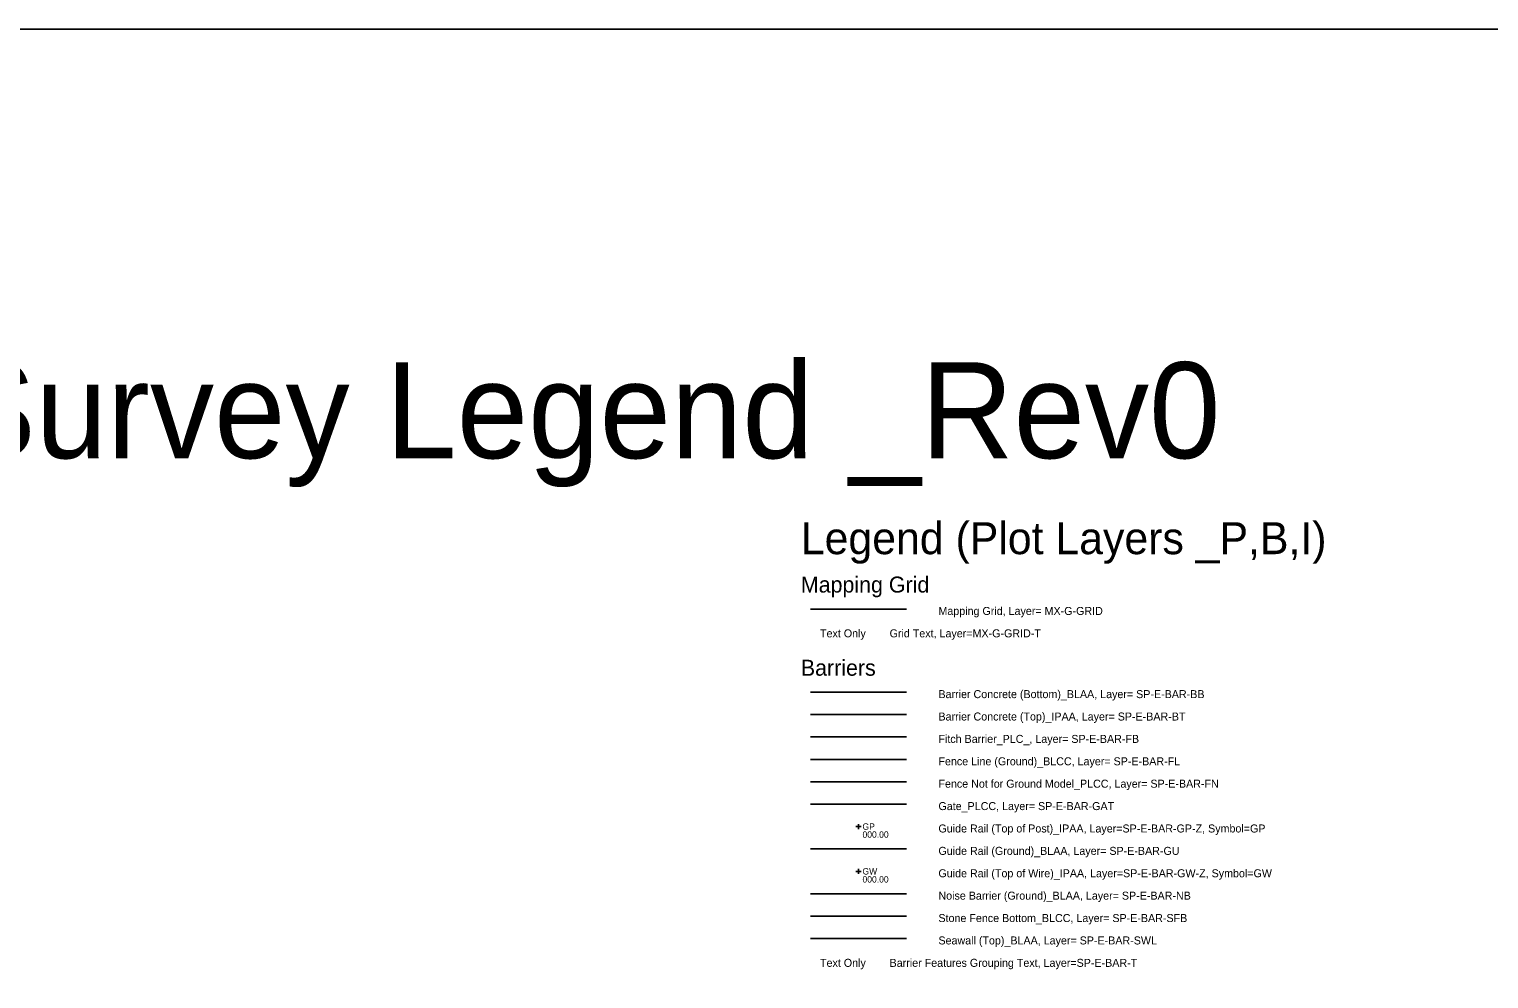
# Model space of a CAD drawing. Extents: x 500528 to 502626, y 4210261 to 4212624.
# Drawn here: x 501142.4 to 501598.5, y 4212327 to 4212623.9 of the extents above; entities that cross this region are included whole.
import ezdxf

# ---------------------------------------------------------------- set-up
doc = ezdxf.new("R2010")
doc.units = 0
for name, color, linetype in [('Default', 7, 'Continuous'), ('MX-G-GRID', 7, 'Continuous'), ('MX-G-GRID-T', 7, 'Continuous'), ('SP-E-BAR-BB', 7, 'Continuous'), ('SP-E-BAR-BT', 7, 'Continuous'), ('SP-E-BAR-FB', 7, 'Continuous'), ('SP-E-BAR-FL', 7, 'Continuous'), ('SP-E-BAR-FN', 7, 'Continuous'), ('SP-E-BAR-GAT', 7, 'Continuous'), ('SP-E-BAR-GP-Z', 7, 'Continuous'), ('SP-E-BAR-GU', 7, 'Continuous'), ('SP-E-BAR-GW-Z', 7, 'Continuous'), ('SP-E-BAR-NB', 7, 'Continuous'), ('SP-E-BAR-SFB', 7, 'Continuous'), ('SP-E-BAR-SWL', 7, 'Continuous'), ('SP-E-BAR-T', 7, 'Continuous')]:
    doc.layers.add(name, color=color, linetype=linetype)

# ---------------------------------------------------------------- blocks, each defined once
blk = doc.blocks.new('GP')
at = {"layer": 'SP-E-BAR-GP-Z'}
for points in [[(-0.08, 0), (0.08, 0)], [(0, -0.08), (0, 0.08)]]:
    blk.add_lwpolyline(points, dxfattribs=at)
at = {"layer": 'SP-E-BAR-T'}
for s, p in [('GP', (0.126, -0.1)), ('000.00', (0.126, -0.35))]:
    blk.add_text(s, height=0.2, dxfattribs=at).set_placement(p)
blk = doc.blocks.new('GW')
at = {"layer": 'SP-E-BAR-GW-Z'}
for points in [[(-0.08, 0), (0.08, 0)], [(0, -0.08), (0, 0.08)]]:
    blk.add_lwpolyline(points, dxfattribs=at)
at = {"layer": 'SP-E-BAR-T'}
for s, p in [('GW', (0.126, -0.1)), ('000.00', (0.126, -0.35))]:
    blk.add_text(s, height=0.2, dxfattribs=at).set_placement(p)

msp = doc.modelspace()

# ---------------------------------------------------------------- linework, layer by layer
at = {"layer": 'Default'}
msp.add_lwpolyline([(500528.35, 4212623.85), (500528.35, 4210260.5), (502626.48, 4210260.5), (502626.48, 4212623.85), (500528.35, 4212623.85)], dxfattribs=at)
msp.add_lwpolyline([(500528.35, 4210260.5), (502626.48, 4210260.5), (502626.48, 4212623.85), (500528.35, 4212623.85)], close=True, dxfattribs=at)
at = {"layer": 'MX-G-GRID'}
msp.add_line((501386.55, 4212442.59), (501416.55, 4212442.59), dxfattribs=at)
at = {"layer": 'SP-E-BAR-BB'}
msp.add_line((501386.55, 4212416.59), (501416.55, 4212416.59), dxfattribs=at)
at = {"layer": 'SP-E-BAR-BT'}
msp.add_line((501386.55, 4212409.59), (501416.55, 4212409.59), dxfattribs=at)
at = {"layer": 'SP-E-BAR-FB'}
msp.add_line((501386.55, 4212402.59), (501416.55, 4212402.59), dxfattribs=at)
at = {"layer": 'SP-E-BAR-FL'}
msp.add_line((501386.55, 4212395.59), (501416.55, 4212395.59), dxfattribs=at)
at = {"layer": 'SP-E-BAR-FN'}
msp.add_line((501386.55, 4212388.59), (501416.55, 4212388.59), dxfattribs=at)
at = {"layer": 'SP-E-BAR-GAT'}
msp.add_line((501386.55, 4212381.59), (501416.55, 4212381.59), dxfattribs=at)
at = {"layer": 'SP-E-BAR-GU'}
msp.add_line((501386.55, 4212367.59), (501416.55, 4212367.59), dxfattribs=at)
at = {"layer": 'SP-E-BAR-NB'}
msp.add_line((501386.55, 4212353.59), (501416.55, 4212353.59), dxfattribs=at)
at = {"layer": 'SP-E-BAR-SFB'}
msp.add_line((501386.55, 4212346.59), (501416.55, 4212346.59), dxfattribs=at)
at = {"layer": 'SP-E-BAR-SWL'}
msp.add_line((501386.55, 4212339.59), (501416.55, 4212339.59), dxfattribs=at)

# ---------------------------------------------------------------- block references
at = {"layer": 'SP-E-BAR-GP-Z', "xscale": 10, "yscale": 10}
msp.add_blockref('GP', (501401.55, 4212374.59), dxfattribs=at)
at = {"layer": 'SP-E-BAR-GW-Z', "xscale": 10, "yscale": 10}
msp.add_blockref('GW', (501401.55, 4212360.59), dxfattribs=at)

# ---------------------------------------------------------------- texts
at = {"layer": 'Default'}
for s, height, p in [('Topographic Survey Legend _Rev0 ', 30, (500883.55, 4212489.74)), ('Legend (Plot Layers _P,B,I) ', 10, (501383.55, 4212459.74)), ('Mapping Grid ', 5, (501383.55, 4212447.74)), ('Barriers ', 5, (501383.55, 4212421.74))]:
    msp.add_text(s, height=height, dxfattribs=at).set_placement(p)
at = {"layer": 'MX-G-GRID'}
msp.add_text('Mapping Grid, Layer= MX-G-GRID ', height=2.5, dxfattribs=at).set_placement((501426.55, 4212440.74))
at = {"layer": 'MX-G-GRID-T'}
msp.add_text('Text Only        Grid Text, Layer=MX-G-GRID-T', height=2.5, dxfattribs=at).set_placement((501389.55, 4212433.74))
at = {"layer": 'SP-E-BAR-BB'}
msp.add_text('Barrier Concrete (Bottom)_BLAA, Layer= SP-E-BAR-BB ', height=2.5, dxfattribs=at).set_placement((501426.55, 4212414.74))
at = {"layer": 'SP-E-BAR-BT'}
msp.add_text('Barrier Concrete (Top)_IPAA, Layer= SP-E-BAR-BT ', height=2.5, dxfattribs=at).set_placement((501426.55, 4212407.74))
at = {"layer": 'SP-E-BAR-FB'}
msp.add_text('Fitch Barrier_PLC_, Layer= SP-E-BAR-FB ', height=2.5, dxfattribs=at).set_placement((501426.55, 4212400.74))
at = {"layer": 'SP-E-BAR-FL'}
msp.add_text('Fence Line (Ground)_BLCC, Layer= SP-E-BAR-FL ', height=2.5, dxfattribs=at).set_placement((501426.55, 4212393.74))
at = {"layer": 'SP-E-BAR-FN'}
msp.add_text('Fence Not for Ground Model_PLCC, Layer= SP-E-BAR-FN ', height=2.5, dxfattribs=at).set_placement((501426.55, 4212386.74))
at = {"layer": 'SP-E-BAR-GAT'}
msp.add_text('Gate_PLCC, Layer= SP-E-BAR-GAT ', height=2.5, dxfattribs=at).set_placement((501426.55, 4212379.74))
at = {"layer": 'SP-E-BAR-GP-Z'}
msp.add_text('Guide Rail (Top of Post)_IPAA, Layer=SP-E-BAR-GP-Z, Symbol=GP ', height=2.5, dxfattribs=at).set_placement((501426.55, 4212372.74))
at = {"layer": 'SP-E-BAR-GU'}
msp.add_text('Guide Rail (Ground)_BLAA, Layer= SP-E-BAR-GU ', height=2.5, dxfattribs=at).set_placement((501426.55, 4212365.74))
at = {"layer": 'SP-E-BAR-GW-Z'}
msp.add_text('Guide Rail (Top of Wire)_IPAA, Layer=SP-E-BAR-GW-Z, Symbol=GW ', height=2.5, dxfattribs=at).set_placement((501426.55, 4212358.74))
at = {"layer": 'SP-E-BAR-NB'}
msp.add_text('Noise Barrier (Ground)_BLAA, Layer= SP-E-BAR-NB ', height=2.5, dxfattribs=at).set_placement((501426.55, 4212351.74))
at = {"layer": 'SP-E-BAR-SFB'}
msp.add_text('Stone Fence Bottom_BLCC, Layer= SP-E-BAR-SFB ', height=2.5, dxfattribs=at).set_placement((501426.55, 4212344.74))
at = {"layer": 'SP-E-BAR-SWL'}
msp.add_text('Seawall (Top)_BLAA, Layer= SP-E-BAR-SWL ', height=2.5, dxfattribs=at).set_placement((501426.55, 4212337.74))
at = {"layer": 'SP-E-BAR-T'}
msp.add_text('Text Only        Barrier Features Grouping Text, Layer=SP-E-BAR-T', height=2.5, dxfattribs=at).set_placement((501389.55, 4212330.74))

doc.saveas('drawing.dxf')
